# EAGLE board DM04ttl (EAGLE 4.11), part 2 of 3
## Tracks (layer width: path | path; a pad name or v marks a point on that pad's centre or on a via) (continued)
DATA_OUT  (via drill 0.61) (continued)
  Bottom 0.254: 44.45,128.27 30.48,128.27 26.67,132.08 IC19.4 | 44.45,128.27 46.35,128.27 46.99,127.64 49.53,127.64 51.44,125.73 58.42,125.73 59.69,124.46 IC21.7 | IC23.7 97.79,124.46 98.42,123.83 v100.33,123.83 102.23,123.83 102.87,123.19 128.27,123.19 129.54,124.46 130.81,124.46 IC25.7 133.35,124.46 135.25,124.46 136.53,123.19 165.1,123.19 166.37,124.46 IC27.7 | 44.45,128.27 44.45,133.35 46.35,133.35 48.9,135.89 69.85,135.89 72.39,138.43 v100.33,138.43
DATA_OUT0\  (via drill 0.61)
  Top 0.254: v179.07,120.65 178.44,120.02 178.44,99.69 176.53,97.79 173.35,97.79 173.35,95.89 173.99,95.25 180.34,95.25 180.34,68.58 178.44,66.67 v178.44,46.99
  Bottom 0.254: 177.16,46.35 176.53,46.99 166.37,46.99 165.74,46.35 164.47,46.35 163.83,45.72 RN13.10 | 177.16,46.35 177.16,43.81 154.31,43.81 153.67,43.18 153.03,43.18 ADDRESS0.X | v179.07,120.65 177.8,120.65 176.53,121.92 IC27.13 | v178.44,46.99 177.8,46.35 177.16,46.35
DATA_OUT1\  (via drill 0.61)
  Top 0.254: v144.78,121.92 146.69,120.02 v146.69,45.72
  Bottom 0.254: 124.46,44.45 123.19,43.18 117.47,43.18 ADDRESS1.X | 124.46,44.45 125.73,45.72 RN15.10 | v144.78,121.92 140.97,121.92 IC25.13 | v146.69,45.72 145.41,44.45 124.46,44.45
DATA_OUT2\  (via drill 0.61)
  Top 0.254: v109.86,45.72 v109.86,121.92
  Bottom 0.254: ADDRESS2.X 81.92,43.18 83.19,44.45 88.9,44.45 90.17,45.72 RN17.10 92.71,45.72 93.34,45.72 94.61,46.99 97.79,46.99 100.33,44.45 108.58,44.45 v109.86,45.72 | v109.86,121.92 105.41,121.92 IC23.13
DATA_OUT3\  (via drill 0.61)
  Top 0.254: v53.98,130.81 57.78,130.81 57.78,83.19 53.34,78.74 53.34,48.26 55.24,46.35 RN19.10
  Bottom 0.254: RN19.10 54.61,45.72 53.98,45.09 48.26,45.09 46.35,43.18 ADDRESS3.X | v53.98,130.81 57.15,130.81 59.69,128.27 62.23,128.27 67.94,122.56 IC21.13
DATA_OUT\  (via drill 0.61)
  Top 0.254: v36.83,187.96 v36.83,138.43
  Bottom 0.254: v36.83,138.43 27.94,138.43 26.67,137.16 IC19.2 | v36.83,187.96 36.83,201.93 208.28,201.93 227.33,182.88 227.33,43.81 218.44,43.81 ADDRESS.X
DB0
  Bottom 0.254: IC30.13 192.41,132.72 191.13,133.99 180.97,133.99 176.53,129.54 IC27.16 173.99,129.54 172.72,130.81 137.16,130.81 | IC21.16 69.85,129.54 71.12,128.27 101.6,128.27 102.87,129.54 IC23.16 105.41,129.54 106.68,130.81 137.16,130.81 | 137.16,130.81 138.43,129.54 IC25.16
DB0-0\
  Top 0.254: IC27.4 166.37,132.08 163.83,134.62 RN1.3
  Bottom 0.254: DATA0.F 153.03,132.08 154.31,133.35 160.02,133.35 161.29,134.62 RN1.3
DB0-1\
  Bottom 0.254: IC25.4 130.81,132.08 128.27,134.62 RN5.3 125.73,134.62 120.02,134.62 117.47,132.08 DATA1.F
DB0-2\
  Bottom 0.254: 94.61,132.72 92.71,134.62 RN7.3 | 94.61,132.72 95.25,132.08 IC23.4 | 94.61,132.72 92.71,130.81 83.19,130.81 81.92,132.08 DATA2.F
DB0-3\
  Bottom 0.254: IC21.4 59.69,132.08 57.15,134.62 RN9.3 54.61,134.62 48.9,134.62 46.35,132.08 DATA3.F
DB0\
  Bottom 0.254: IC30.15 198.75,131.44 200.03,130.18 214.63,130.18 215.26,130.81 216.53,130.81 217.81,132.08 DATA.F
DB1  (via drill 0.61)
  Top 0.254: v185.42,125.73 185.42,128.27 187.96,130.81 IC30.11
  Bottom 0.254: IC21.12 69.85,119.38 71.12,120.65 100.33,120.65 101.6,119.38 102.87,119.38 IC23.12 105.41,119.38 106.68,120.65 136.53,120.65 137.79,119.38 138.43,119.38 IC25.12 140.97,119.38 142.24,120.65 172.72,120.65 173.99,119.38 IC27.12 176.53,119.38 179.07,119.38 v185.42,125.73
DB1-0\
  Top 0.254: IC27.8 167,122.56 165.74,123.83 165.74,131.44 163.83,133.35 160.66,133.35 160.66,131.44 161.93,130.18 RN1.5
  Bottom 0.254: DATA0.L 153.03,127 154.31,128.27 157.48,128.27 158.75,129.54 161.29,129.54 RN1.5
DB1-1\  (via drill 0.61)
  Top 0.254: v133.99,114.3 133.99,120.02 132.72,121.28 IC25.8 | v128.27,114.94 128.91,115.57 128.91,127.64 127.64,128.91 RN5.5
  Bottom 0.254: v133.99,114.3 133.35,114.94 v128.27,114.94 | DATA1.L 117.47,127 120.02,129.54 125.73,129.54 RN5.5
DB1-2\  (via drill 0.61)
  Top 0.254: 89.53,129.54 85.09,129.54 v85.09,127 | 89.53,129.54 90.17,129.54 RN7.5 | v99.06,114.3 99.06,119.38 97.16,121.28 IC23.8 | v90.81,114.94 89.53,116.2 89.53,129.54
  Bottom 0.254: v85.09,127 81.92,127 DATA2.L | v99.06,114.3 98.42,114.94 v90.81,114.94
DB1-3\  (via drill 0.61)
  Top 0.254: v49.53,126.36 49.53,129.54 54.61,129.54 RN9.5
  Bottom 0.254: IC21.8 59.69,121.92 58.42,123.19 48.9,123.19 46.35,120.65 45.09,120.65 44.45,121.28 44.45,127 45.09,127 DATA3.L 46.35,127 48.9,127 v49.53,126.36
DB1\
  Bottom 0.254: IC30.9 183.51,131.44 186.69,128.27 216.53,128.27 217.81,127 DATA.L
DB2  (via drill 0.61)
  Top 0.254: v189.23,104.14 189.23,111.76 193.04,115.57 IC29.4
  Bottom 0.254: IC20.5 62.23,96.52 63.5,95.25 93.98,95.25 95.25,96.52 IC22.5 97.79,96.52 99.06,95.25 128.91,95.25 130.18,96.52 130.81,96.52 IC24.5 133.35,96.52 134.62,95.25 165.1,95.25 | 165.1,95.25 166.37,96.52 IC26.5 | v189.23,104.14 180.34,95.25 165.1,95.25
DB2-0\  (via drill 0.61)
  Top 0.254: v172.72,111.76 172.72,95.25 173.99,93.98 IC26.15 | v163.83,114.94 164.47,115.57 164.47,122.56 163.19,123.83 RN1.7 161.29,124.46 v158.75,121.92
  Bottom 0.254: v172.72,111.76 169.54,114.94 v163.83,114.94 | v158.75,121.92 153.03,121.92 DATA0.R
DB2-1\  (via drill 0.61)
  Top 0.254: RN5.7 125.73,124.46 v123.19,121.92 123.19,116.84 v128.27,111.76 | v137.16,107.31 137.16,96.52 139.06,94.61 IC24.15
  Bottom 0.254: v123.19,121.92 117.47,121.92 DATA1.R | v137.16,107.31 132.72,111.76 v128.27,111.76
DB2-2\  (via drill 0.61)
  Top 0.254: v101.6,120.65 101.6,96.52 103.5,94.61 IC22.15 | v88.27,124.46 v88.27,121.92
  Bottom 0.254: v101.6,120.65 99.06,123.19 93.98,123.19 92.71,124.46 RN7.7 90.17,124.46 v88.27,124.46 | v88.27,121.92 81.92,121.92 DATA2.R
DB2-3\  (via drill 0.61)
  Top 0.254: v66.04,119.38 66.04,114.3 65.41,113.67 65.41,97.16 67.94,94.61 IC20.15
  Bottom 0.254: v66.04,119.38 62.23,123.19 59.69,123.19 58.42,124.46 57.15,124.46 RN9.7 55.24,123.83 48.26,123.83 46.35,121.92 DATA3.R
DB2\  (via drill 0.61)
  Top 0.254: v201.93,120.65 198.75,117.47 IC29.2
  Bottom 0.254: v201.93,120.65 216.53,120.65 217.81,121.92 DATA.R
DB3
  Bottom 0.254: IC29.11 187.32,108.58 186.06,107.31 182.25,107.31 176.53,101.6 IC26.18 173.99,101.6 172.72,102.87 137.16,102.87 | 101.6,102.87 71.12,102.87 69.85,101.6 IC20.18 | 101.6,102.87 102.87,101.6 IC22.18 | 137.16,102.87 138.43,101.6 IC24.18 | 137.16,102.87 101.6,102.87
DB3-0\  (via drill 0.61)
  Top 0.254: 160.66,116.84 160.66,117.47 161.93,118.75 RN1.9 | 160.66,116.84 160.66,116.2 164.47,112.39 164.47,107.31 167,104.78 IC26.2 | v160.02,116.84 160.66,116.84
  Bottom 0.254: v160.02,116.84 153.03,116.84 DATA0.V
DB3-1\  (via drill 0.61)
  Top 0.254: v134.62,106.68 132.72,104.78 IC24.2 | v124.46,116.84 126.36,118.75 RN5.9
  Bottom 0.254: v134.62,106.68 133.35,107.95 132.72,107.95 130.81,109.86 130.18,109.86 128.27,107.95 122.56,107.95 117.47,113.03 116.2,113.03 115.57,113.67 115.57,116.84 116.2,116.84 DATA1.V 117.47,116.84 v124.46,116.84
DB3-2\  (via drill 0.61)
  Top 0.254: v100.33,108.58 v100.33,104.14 | v85.72,119.38 84.45,118.11 v84.45,116.84
  Bottom 0.254: v100.33,104.14 97.79,104.14 IC22.2 | v100.33,108.58 98.42,110.49 84.45,110.49 81.92,113.03 80.64,113.03 80.01,113.67 80.01,116.84 80.64,116.84 DATA2.V 81.92,116.84 v84.45,116.84 | v85.72,119.38 90.17,119.38 RN7.9
DB3-3\  (via drill 0.61)
  Top 0.254: v63.5,119.38 63.5,106.68 61.59,104.78 IC20.2
  Bottom 0.254: v63.5,119.38 62.23,120.65 58.42,120.65 57.15,119.38 RN9.9 55.24,118.75 48.26,118.75 46.35,116.84 DATA3.V
DB3\  (via drill 0.61)
  Top 0.254: v189.23,120.02 189.23,115.57 183.51,109.86 IC29.9
  Bottom 0.254: v189.23,120.02 189.87,119.38 214,119.38 215.26,118.11 216.53,118.11 217.81,116.84 DATA.V
DB4
  Top 0.254: IC26.16 176.53,96.52 186.69,106.68 186.69,111.76 190.5,115.57 IC29.5
  Bottom 0.254: 101.6,97.79 71.12,97.79 69.85,96.52 IC20.16 | 101.6,97.79 102.87,96.52 IC22.16 | 137.16,97.79 138.43,96.52 IC24.16 | 137.16,97.79 101.6,97.79 | 137.16,97.79 172.72,97.79 173.99,96.52 IC26.16
DB4-0\
  Top 0.254: IC26.4 167,99.69 164.47,102.23 164.47,104.78 163.19,106.05 RN2.2
  Bottom 0.254: DATA0.Z 153.03,111.76 155.57,109.22 158.75,109.22 161.29,106.68 RN2.2
DB4-1\  (via drill 0.61)
  Top 0.254: v130.81,108.58 130.18,107.95 130.18,100.97 131.44,99.69 IC24.4
  Bottom 0.254: v130.81,108.58 128.91,106.68 128.27,106.68 RN6.2 125.73,106.68 122.56,106.68 117.47,111.76 DATA1.Z
DB4-2\  (via drill 0.61)
  Top 0.254: v99.06,106.68 99.06,101.6 97.16,99.69 IC22.4
  Bottom 0.254: v99.06,106.68 97.79,107.95 93.98,107.95 92.71,106.68 RN8.2 90.17,106.68 87,109.86 83.82,109.86 81.92,111.76 DATA2.Z
DB4-3\  (via drill 0.61)
  Top 0.254: v59.69,108.58 59.05,107.95 59.05,100.97 60.33,99.69 IC20.4 | v49.53,106.68 49.53,107.31 45.72,111.12 DATA3.Z
  Bottom 0.254: v59.69,108.58 57.78,106.68 57.15,106.68 RN10.2 54.61,106.68 v49.53,106.68
DB4\
  Bottom 0.254: IC29.7 186.06,116.2 189.23,113.03 216.53,113.03 217.81,111.76 DATA.Z
DB5  (via drill 0.61)
  Top 0.254: v179.07,87 177.16,88.9 177.16,89.53 175.9,90.81 IC26.14
  Bottom 0.254: IC20.14 69.85,91.44 71.12,92.71 101.6,92.71 102.87,91.44 IC22.14 105.41,91.44 106.68,92.71 135.89,92.71 137.16,91.44 138.43,91.44 IC24.14 140.97,91.44 142.24,92.71 172.72,92.71 173.99,91.44 IC26.14 | v179.07,87 189.87,87 192.41,84.45 IC28.13
DB5-0\  (via drill 0.61)
  Top 0.254: IC26.6 168.28,94.61 169.54,95.89 v169.54,105.41 169.54,107.31 168.91,107.95 165.1,107.95 165.1,129.54 163.19,131.44 RN1.4
  Bottom 0.254: v169.54,105.41 154.31,105.41 153.03,106.68 DATA0.DD
DB5-1\  (via drill 0.61)
  Top 0.254: 123.19,139.7 124.46,138.43 124.46,134.62 126.36,132.72 RN5.4 | 123.19,139.7 115.57,139.7 115.57,111.12 116.2,110.49 118.11,110.49 118.11,108.58 116.84,107.31 DATA1.DD | v135.25,140.97 135.25,120.02 135.89,119.38 135.89,97.79 132.72,94.61 IC24.6 | v124.46,140.97 123.19,139.7
  Bottom 0.254: v135.25,140.97 v124.46,140.97
DB5-2\  (via drill 0.61)
  Top 0.254: v97.79,77.47 97.79,82.55 98.42,83.19 98.42,92.08 97.16,93.34 IC22.6 | v74.3,77.47 v74.3,106.68 | v82.55,133.35 82.55,108.58 81.28,107.31 DATA2.DD
  Bottom 0.254: v74.3,77.47 v97.79,77.47 | v74.3,106.68 75.56,107.95 79.38,107.95 80.64,106.68 DATA2.DD | v82.55,133.35 88.9,133.35 90.17,132.08 RN7.4
DB5-3\  (via drill 0.61)
  Top 0.254: v71.75,106.68 71.75,92.71 67.31,92.71 64.77,95.25 64.77,99.06 63.5,99.06 62.23,97.79 62.87,97.16 62.87,95.89 61.59,94.61 IC20.6 | RN9.4 54.61,132.08 46.99,132.08 46.99,131.44 46.35,130.81 44.45,130.81 44.45,108.58 45.72,107.31 DATA3.DD
  Bottom 0.254: v71.75,106.68 70.48,107.95 61.59,107.95 59.69,109.86 59.05,109.86 57.15,107.95 47.62,107.95 46.35,106.68 DATA3.DD
DB5\
  Bottom 0.254: IC28.15 198.75,84.45 203.2,88.9 214,88.9 215.26,90.17 219.07,90.17 219.71,90.81 219.71,106.05 218.44,106.05 DATA.DD
DB6
  Bottom 0.254: IC20.7 62.23,91.44 63.5,90.17 93.34,90.17 94.61,91.44 95.25,91.44 IC22.7 97.79,91.44 98.42,90.81 102.23,90.81 102.87,90.17 129.54,90.17 130.81,91.44 IC24.7 133.35,91.44 134.62,90.17 165.1,90.17 | 165.1,90.17 166.37,91.44 IC26.7 | 165.1,90.17 176.53,90.17 177.16,89.53 191.13,89.53 192.41,90.81 IC28.4
DB6-0\  (via drill 0.61)
  Top 0.254: v170.18,88.27 169.54,87.63 166.37,87.63 165.1,88.9 165.1,93.98 163.19,95.89 RN2.6 | v156.21,101.6 157.48,100.33 v157.48,96.52
  Bottom 0.254: v170.18,88.27 170.81,88.9 173.99,88.9 IC26.13 | v156.21,101.6 153.03,101.6 DATA0.JJ | v157.48,96.52 161.29,96.52 RN2.6
DB6-1\  (via drill 0.61)
  Top 0.254: 121.28,97.79 117.47,101.6 DATA1.JJ | 121.28,97.79 v122.56,96.52 | v141.6,79.38 141.6,87 140.34,88.27 IC24.13 | v128.27,79.38 121.28,86.36 121.28,97.79
  Bottom 0.254: v122.56,96.52 125.73,96.52 RN6.6 | v128.27,79.38 v141.6,79.38
DB6-2\  (via drill 0.61)
  Top 0.254: v88.27,101.6 88.27,99.69 90.81,97.16 RN8.6 | v101.6,81.28 101.6,86.36 103.5,88.27 IC22.13 | v84.45,82.55 83.82,83.19 83.82,93.34 83.19,93.98 83.19,99.06 81.28,100.97 DATA2.JJ
  Bottom 0.254: v88.27,101.6 81.92,101.6 DATA2.JJ | v101.6,81.28 100.33,80.01 87,80.01 v84.45,82.55
DB6-3\  (via drill 0.61)
  Top 0.254: v66.04,91.44 67.94,89.53 IC20.13 | v50.16,96.52 v50.16,100.97
  Bottom 0.254: v66.04,91.44 62.23,95.25 58.42,95.25 57.15,96.52 RN10.6 54.61,96.52 v50.16,96.52 | v50.16,100.97 46.99,100.97 46.35,101.6 DATA3.JJ
DB6\  (via drill 0.61)
  Top 0.254: v204.47,97.79 198.75,92.08 IC28.2
  Bottom 0.254: v204.47,97.79 207.01,100.33 216.53,100.33 217.81,101.6 DATA.JJ
DB7  (via drill 0.61)
  Top 0.254: v71.75,77.47 71.75,83.19 69.22,85.72 IC20.12
  Bottom 0.254: 177.16,85.72 175.9,85.72 IC26.12 | 177.16,85.72 186.06,85.72 187.32,84.45 IC28.11 | v71.75,77.47 73.03,76.2 103.5,76.2 107.95,80.64 107.95,82.55 | 107.95,82.55 107.95,85.72 104.78,85.72 IC22.12 | 141.6,81.28 141.6,80.64 120.65,80.64 118.75,82.55 107.95,82.55 | 141.6,81.28 141.6,84.45 140.34,85.72 IC24.12 | 177.16,85.72 177.16,81.28 141.6,81.28
DB7-0\  (via drill 0.61)
  Top 0.254: IC26.8 167,89.53 165.74,90.81 165.74,98.42 163.19,100.97 RN2.4 161.93,100.97 158.75,97.79 158.75,95.25 157.48,95.25 v156.21,96.52
  Bottom 0.254: v156.21,96.52 153.03,96.52 DATA0.NN
DB7-1\  (via drill 0.61)
  Top 0.254: 125.09,95.25 125.09,99.69 126.36,100.97 RN6.4 | v125.09,87.63 125.09,95.25 | 125.09,95.25 117.47,102.87 116.2,102.87 115.57,102.23 115.57,98.42 116.84,97.16 DATA1.NN
  Bottom 0.254: v125.09,87.63 129.54,87.63 130.81,88.9 IC24.8
DB7-2\  (via drill 0.61)
  Top 0.254: v82.55,87.63 82.55,94.61 81.28,95.89 DATA2.NN | v88.9,87.63 88.9,80.01 92.08,80.01 93.34,81.28 93.34,99.69 92.08,100.97 RN8.4
  Bottom 0.254: v82.55,87.63 v88.9,87.63 93.98,87.63 95.25,88.9 IC22.8
DB7-3\  (via drill 0.61)
  Top 0.254: v53.98,92.71 v53.98,97.79 53.98,99.69 55.24,100.97 RN10.4
  Bottom 0.254: v53.98,92.71 57.15,92.71 60.33,89.53 IC20.8 | v53.98,97.79 47.62,97.79 46.35,96.52 DATA3.NN
DB7\  (via drill 0.61)
  Top 0.254: v189.23,94.61 189.23,90.17 183.51,84.45 IC28.9
  Bottom 0.254: v189.23,94.61 189.87,95.25 216.53,95.25 217.81,96.52 DATA.NN
DB8  (via drill 0.61)
  Top 0.254: v188.59,88.27 190.5,90.17 IC28.5
  Bottom 0.254: IC20.9 62.23,86.36 62.87,85.72 66.67,85.72 67.31,85.09 93.98,85.09 95.25,86.36 IC22.9 97.79,86.36 99.06,87.63 107.31,87.63 109.86,85.09 129.54,85.09 130.81,86.36 IC24.9 133.35,86.36 134.62,87.63 140.97,87.63 143.51,85.09 163.83,85.09 164.47,85.72 165.74,85.72 166.37,86.36 IC26.9 168.28,85.72 170.18,85.72 172.09,87.63 176.53,87.63 177.16,88.27 v188.59,88.27
DB8-0\  (via drill 0.61)
  Top 0.254: v165.1,82.55 163.19,84.45 163.19,85.72 RN2.10 161.29,86.36 160.66,86.36 159.38,87.63 v159.38,91.44
  Bottom 0.254: v165.1,82.55 172.72,82.55 173.99,83.82 IC26.11 | v159.38,91.44 153.03,91.44 DATA0.TT
DB8-1\  (via drill 0.61)
  Top 0.254: v122.56,91.44 122.56,86.36 125.73,86.36 RN6.10 127.64,85.72 127.64,83.19 v128.27,82.55
  Bottom 0.254: v122.56,91.44 117.47,91.44 DATA1.TT | v128.27,82.55 137.16,82.55 138.43,83.82 IC24.11
DB8-2\  (via drill 0.61)
  Top 0.254: v88.27,91.44 88.27,89.53 90.81,87 RN8.10 92.08,85.72 v92.08,81.28
  Bottom 0.254: v88.27,91.44 81.92,91.44 DATA2.TT | v92.08,81.28 100.33,81.28 102.87,83.82 IC22.11
DB8-3\
  Bottom 0.254: DATA3.TT 46.35,91.44 49.53,88.27 52.7,88.27 54.61,86.36 RN10.10 57.15,86.36 58.42,85.09 66.04,85.09 67.31,83.82 IC20.11
DB8\
  Bottom 0.254: IC28.7 186.06,92.08 187.32,93.34 214.63,93.34 215.26,92.71 216.53,92.71 217.81,91.44 DATA.TT
DB9
  Bottom 0.254: IC30.4 192.41,139.06 191.13,137.79 179.71,137.79 176.53,134.62 IC27.18 173.99,134.62 172.72,135.89 137.16,135.89 | 101.6,135.89 71.12,135.89 69.85,134.62 IC21.18 | 101.6,135.89 102.87,134.62 IC23.18 | 137.16,135.89 138.43,134.62 IC25.18 | 137.16,135.89 101.6,135.89
DB9-0\  (via drill 0.61)
  Top 0.254: v160.02,134.62 161.93,136.53 RN1.2
  Bottom 0.254: RN1.2 163.83,137.16 166.37,137.16 IC27.2 | v160.02,134.62 153.03,134.62 DATA0.D
DB9-1\  (via drill 0.61)
  Top 0.254: v120.02,137.16 117.47,134.62 DATA1.D
  Bottom 0.254: IC25.2 130.81,137.16 128.27,137.16 RN5.2 125.73,137.16 v120.02,137.16
DB9-2\  (via drill 0.61)
  Top 0.254: v85.72,134.62 v88.27,137.16
  Bottom 0.254: IC23.2 95.25,137.16 92.71,137.16 RN7.2 90.17,137.16 v88.27,137.16 | v85.72,134.62 81.92,134.62 DATA2.D
DB9-3\
  Bottom 0.254: IC21.2 59.69,137.16 57.15,137.16 RN9.2 54.61,137.16 48.9,137.16 46.35,134.62 DATA3.D
DB9\
  Bottom 0.254: IC30.2 198.75,139.06 201.93,135.89 216.53,135.89 217.81,134.62 DATA.D
DB10  (via drill 0.61)
  Top 0.254: v184.15,129.54 184.15,133.35 189.87,139.06 IC30.5
  Bottom 0.254: 101.6,125.73 71.12,125.73 69.85,124.46 IC21.14 | 101.6,125.73 102.87,124.46 IC23.14 | 137.16,125.73 138.43,124.46 IC25.14 | 137.16,125.73 101.6,125.73 | 137.16,125.73 168.91,125.73 169.54,125.09 173.35,125.09 173.99,124.46 IC27.14 176.53,124.46 179.07,124.46 v184.15,129.54
DB10-0\  (via drill 0.61)
  Top 0.254: v164.47,84.45 164.47,89.53 163.19,90.81 RN2.8 | v171.45,85.09 171.45,123.19 172.09,123.83 v172.09,126.36 | v158.75,128.27 v157.48,129.54
  Bottom 0.254: v164.47,84.45 165.1,85.09 v171.45,85.09 | v172.09,126.36 171.45,127 168.91,127 IC27.6 166.37,127 165.74,127 164.47,128.27 v158.75,128.27 | v157.48,129.54 153.03,129.54 DATA0.J
DB10-1\  (via drill 0.61)
  Top 0.254: 118.11,129.54 118.75,128.91 118.75,107.95 128.27,107.95 128.91,107.31 128.91,93.34 127.64,92.08 RN6.8 | 118.11,129.54 117.47,129.54 DATA1.J | v133.99,138.43 133.99,128.91 132.72,127.64 IC25.6 | v123.19,138.43 118.11,133.35 118.11,129.54
  Bottom 0.254: v133.99,138.43 v123.19,138.43
DB10-2\  (via drill 0.61)
  Top 0.254: 87,113.67 87,123.19 83.82,126.36 83.82,133.99 81.92,135.89 80.01,135.89 80.01,131.44 81.28,130.18 DATA2.J | 87,113.67 87,99.69 89.53,97.16 89.53,93.34 90.81,92.08 RN8.8 | v100.33,114.3 100.33,119.38 99.06,120.65 99.06,124.46 97.16,126.36 IC23.6 | 87,113.67 v88.27,113.67
  Bottom 0.254: v100.33,114.3 99.06,113.03 98.42,113.03 97.16,114.3 91.44,114.3 90.81,113.67 v88.27,113.67
DB10-3\
  Top 0.254: RN10.8 54.61,91.44 52.07,91.44 52.07,113.03 52.7,113.67 52.7,121.92 45.72,128.91 DATA3.J
  Bottom 0.254: IC21.6 59.69,127 58.42,128.27 47.62,128.27 46.35,129.54 DATA3.J
DB10\
  Bottom 0.254: IC30.7 186.06,140.34 187.32,141.6 215.9,141.6 219.71,137.79 219.71,130.18 218.44,130.18 DATA.J
DB11
  Bottom 0.254: IC20.3 62.23,101.6 62.87,100.97 66.67,100.97 67.31,100.33 93.34,100.33 94.61,101.6 95.25,101.6 IC22.3 97.79,101.6 99.06,100.33 128.91,100.33 130.18,101.6 130.81,101.6 IC24.3 133.35,101.6 134.62,100.33 165.1,100.33 | 165.1,100.33 166.37,101.6 IC26.3 | 165.1,100.33 184.15,100.33 192.41,108.58 IC29.13
DB11-0\  (via drill 0.61)
  Top 0.254: IC26.17 175.9,99.69 177.8,101.6 177.8,144.15 169.54,152.4 163.83,152.4 163.83,143.51 158.75,138.43 158.75,130.81 161.93,127.64 RN1.6 161.29,127 v158.75,124.46
  Bottom 0.254: v158.75,124.46 153.03,124.46 DATA0.N
DB11-1\  (via drill 0.61)
  Top 0.254: v123.19,124.46 125.73,127 RN5.6 | v143.51,128.27 v143.51,99.06
  Bottom 0.254: v123.19,124.46 117.47,124.46 DATA1.N | v143.51,99.06 140.97,99.06 IC24.17 | v143.51,128.27 129.54,128.27 128.27,127 RN5.6
DB11-2\  (via drill 0.61)
  Top 0.254: v106.68,82.55 106.68,96.52 104.78,98.42 IC22.17 | v77.47,80.64 v77.47,123.19 | v88.27,127 87,125.73 v87,124.46
  Bottom 0.254: v106.68,82.55 103.5,79.38 78.74,79.38 v77.47,80.64 | v77.47,123.19 79.38,123.19 80.64,124.46 DATA2.N 81.92,124.46 v87,124.46 | v88.27,127 90.17,127 RN7.6
DB11-3\  (via drill 0.61)
  Top 0.254: v53.34,100.33 53.98,100.97 53.98,125.09 | 53.98,125.09 55.24,126.36 RN9.6 | 53.98,125.09 v50.8,125.09
  Bottom 0.254: v53.34,100.33 66.04,100.33 67.31,99.06 IC20.17 | v50.8,125.09 46.99,125.09 46.35,124.46 DATA3.N
DB11\
  Bottom 0.254: IC29.15 198.75,108.58 200.03,107.31 212.09,107.31 215.26,110.49 219.07,110.49 220.34,111.76 220.34,123.83 218.44,123.83 DATA.N
GND  (via drill 0.61)
  Top 0.635: v64.14,134.62 64.14,139.7 62.23,141.6 C21.2 | DATA2.B 80.64,137.16 79.38,137.16 DATA2.A 78.74,136.53 78.74,135.25 DATA2.C 78.74,133.99 78.74,132.72 DATA2.E 78.74,131.44 78.74,130.18 DATA2.H 78.74,128.91 78.74,127.64 DATA2.K 78.74,126.36 78.74,125.09 DATA2.M 78.74,123.83 78.74,122.56 DATA2.P 78.74,121.28 78.74,120.02 DATA2.S 78.74,118.75 78.74,117.47 DATA2.U 78.74,116.2 78.74,114.94 DATA2.W 78.74,113.67 78.74,112.39 DATA2.Y 78.74,111.12 78.74,109.86 DATA2.AA 78.74,108.58 78.74,107.31 DATA2.CC 78.74,106.05 78.74,104.78 DATA2.EE 78.74,103.5 78.74,102.23 DATA2.HH 78.74,100.97 78.74,99.69 DATA2.KK 78.74,98.42 78.74,97.16 DATA2.MM 78.74,95.89 78.74,94.61 DATA2.PP 78.74,93.34 78.74,92.08 DATA2.SS 78.74,90.81 78.74,89.53 DATA2.UU 78.74,88.27 v78.74,83.82 78.74,66.67 ADDRESS2.A | C20.2 62.23,109.86 v62.23,111.76 62.23,116.84 IC21.10 | IC8.10 95.89,12.06 94.61,10.79 94.61,7.62 C96.- 92.71,6.99 78.74,6.99 78.74,17.14 ADDRESS2.UU 78.74,18.41 78.74,19.68 ADDRESS2.SS 78.74,20.95 78.74,22.23 ADDRESS2.PP 78.74,23.5 78.74,24.77 ADDRESS2.MM 78.74,26.04 78.74,27.3 ADDRESS2.KK 78.74,28.57 78.74,29.84 ADDRESS2.HH 78.74,31.11 78.74,32.38 ADDRESS2.EE 78.74,33.66 78.74,34.92 ADDRESS2.CC 78.74,36.2 78.74,37.47 ADDRESS2.AA 78.74,38.73 78.74,40.01 ADDRESS2.Y 78.74,41.27 78.74,42.55 ADDRESS2.W 78.74,43.81 78.74,45.09 ADDRESS2.U 78.74,46.35 78.74,47.62 ADDRESS2.S 78.74,48.9 78.74,50.16 ADDRESS2.P 78.74,51.44 78.74,52.7 ADDRESS2.M 78.74,53.98 78.74,55.24 ADDRESS2.K 78.74,56.52 78.74,57.78 ADDRESS2.H 78.74,59.05 78.74,60.33 ADDRESS2.E 78.74,61.59 78.74,62.87 ADDRESS2.C 78.74,64.14 78.74,65.41 ADDRESS2.A
  Top 0.635: 61.59,40.64 61.59,45.09 IC7.10 | 61.59,40.64 61.59,39.37 62.23,38.73 C6.2 | ADDRESS2.B 80.64,66.04 79.38,66.04 ADDRESS2.A | v62.23,40.64 61.59,40.64 | 10.79,32.38 10.79,23.5 12.7,21.59 IC3.8 | 10.79,32.38 12.7,34.29 IC1.7 12.7,36.83 12.7,38.1 16.51,38.1 20.32,41.91 IC4.12 | 10.79,47.62 12.7,49.53 IC4.8 | 10.79,32.38 10.79,47.62 | 10.79,47.62 10.79,62.87 12.7,64.77 IC2.7 | ADDRESS3.VV 45.09,17.78 43.81,17.78 ADDRESS3.UU 43.18,18.41 43.18,19.68 ADDRESS3.SS 43.18,20.95 43.18,22.23 ADDRESS3.PP 43.18,23.5 43.18,24.77 ADDRESS3.MM 43.18,26.04 43.18,27.3 ADDRESS3.KK 43.18,28.57 43.18,29.84 ADDRESS3.HH 43.18,31.11 43.18,32.38 ADDRESS3.EE 43.18,33.66 43.18,34.92 ADDRESS3.CC 43.18,36.2 43.18,37.47 ADDRESS3.AA 43.18,38.73 43.18,40.01 ADDRESS3.Y 43.18,41.27 43.18,42.55 ADDRESS3.W 43.18,43.81 43.18,45.09 ADDRESS3.U 43.18,46.35 43.18,47.62 ADDRESS3.S 43.18,48.9 43.18,50.16 ADDRESS3.P 43.18,51.44 43.18,52.7 ADDRESS3.M 43.18,53.98 43.18,55.24 ADDRESS3.K 43.18,56.52 43.18,57.78 ADDRESS3.H 43.18,59.05 43.18,60.33 ADDRESS3.E 43.18,61.59 43.18,62.87 ADDRESS3.C 43.18,64.14 43.18,65.41 ADDRESS3.A 43.18,66.67 43.18,88.27 DATA3.UU | IC31.5 58.42,194.31 57.15,195.58 50.8,195.58 50.8,194.31 IC31.8 50.8,191.77 50.8,191.13 48.26,188.59 48.26,178.44 45.72,175.9 SV1.2 45.09,175.26 43.18,173.35 43.18,137.79 DATA3.A | DATA3.A 43.18,136.53 43.18,135.25 DATA3.C 43.18,133.99 43.18,132.72 DATA3.E 43.18,131.44 43.18,130.18 DATA3.H 43.18,128.91 43.18,127.64 DATA3.K 43.18,126.36 43.18,125.09 DATA3.M 43.18,123.83 43.18,122.56 DATA3.P 43.18,121.28 43.18,120.02 DATA3.S 43.18,118.75 43.18,117.47 DATA3.U 43.18,116.2 43.18,114.94 DATA3.W 43.18,113.67 43.18,112.39 DATA3.Y 43.18,111.12 43.18,109.86 DATA3.AA 43.18,108.58 43.18,107.31 DATA3.CC 43.18,106.05 43.18,104.78 DATA3.EE 43.18,103.5 43.18,102.23 DATA3.HH 43.18,100.97 43.18,99.69 DATA3.KK 43.18,98.42 43.18,97.16 DATA3.MM 43.18,95.89 43.18,94.61 DATA3.PP 43.18,93.34 43.18,92.08 DATA3.SS 43.18,90.81 43.18,89.53 DATA3.UU
  Top 0.635: DATA3.A 43.81,137.16 45.09,137.16 DATA3.B 45.72,137.79 50.8,142.88 50.8,158.75 53.34,161.29 IC34.7 | C19.2 26.67,141.6 26.67,140.97 26.04,140.34 IC19.1 26.67,139.7 27.94,138.43 27.94,123.19 26.67,121.92 IC19.8 26.04,121.28 26.67,120.65 26.67,109.86 C18.2 26.67,108.58 26.67,107.95 26.04,107.31 IC18.1 | C9.2 97.79,71.75 96.52,73.03 96.52,83.19 IC22.10 | C7.2 62.23,71.75 62.23,83.82 IC20.10 | DATA3.UU 43.81,88.9 45.09,88.9 DATA3.VV | 168.28,42.55 168.28,45.09 IC13.10 | 168.28,42.55 168.28,39.37 168.91,38.73 C12.2 | 190.5,29.21 182.88,21.59 IC14.8 | 190.5,29.21 190.5,36.83 IC15.12 | v171.45,42.55 168.28,42.55 | IC16.12 190.5,62.23 200.66,52.07 200.66,46.99 IC15.1 | 190.5,80.01 182.88,72.39 IC16.8 | 190.5,80.01 190.5,82.55 IC28.12 190.5,85.09 194.31,88.9 200.03,88.9 200.03,90.81 IC28.1 | ADDRESS.UU 215.9,18.41 215.9,19.68 ADDRESS.SS 215.9,20.95 215.9,22.23 ADDRESS.PP 215.9,23.5 215.9,24.77 ADDRESS.MM 215.9,26.04 215.9,27.3 ADDRESS.KK 215.9,28.57 215.9,29.84 ADDRESS.HH 215.9,31.11 215.9,32.38 ADDRESS.EE 215.9,33.66 215.9,34.92 ADDRESS.CC 215.9,36.2 215.9,37.47 ADDRESS.AA 215.9,38.73 215.9,40.01 ADDRESS.Y 215.9,41.27 215.9,42.55 ADDRESS.W 215.9,43.81 215.9,45.09 ADDRESS.U 215.9,46.35 215.9,47.62 ADDRESS.S 215.9,48.9 215.9,50.16 ADDRESS.P 215.9,51.44 215.9,52.7 ADDRESS.M 215.9,53.98 215.9,55.24 ADDRESS.K 215.9,56.52 215.9,57.78 ADDRESS.H 215.9,59.05 215.9,60.33 ADDRESS.E 215.9,61.59 215.9,62.87 ADDRESS.C 215.9,64.14 215.9,65.41 ADDRESS.A 216.53,66.04 217.81,66.04 ADDRESS.B | 190.5,80.01 200.66,80.01 200.66,72.39 IC16.1 | 190.5,29.21 200.66,29.21 200.66,21.59 IC14.1
  Top 0.635: IC28.8 182.88,92.71 190.5,100.33 190.5,107.95 IC29.12 190.5,110.49 194.31,114.3 200.03,114.3 200.03,116.2 IC29.1 201.29,116.2 201.29,115.57 202.56,114.3 C29.2 | DATA.UU 215.9,89.53 215.9,90.81 DATA.SS 215.9,92.08 215.9,93.34 DATA.PP 215.9,94.61 215.9,95.89 DATA.MM 215.9,97.16 215.9,98.42 DATA.KK 215.9,99.69 215.9,100.97 DATA.HH 215.9,102.23 215.9,103.5 DATA.EE 215.9,104.78 215.9,106.05 DATA.CC 215.9,107.31 215.9,108.58 DATA.AA 215.9,109.86 215.9,111.12 DATA.Y 215.9,112.39 215.9,113.67 DATA.W 215.9,114.94 215.9,116.2 DATA.U 215.9,117.47 215.9,118.75 DATA.S 215.9,120.02 215.9,121.28 DATA.P 215.9,122.56 215.9,123.83 DATA.M 215.9,125.09 215.9,126.36 DATA.K 215.9,127.64 215.9,128.91 DATA.H 215.9,130.18 215.9,131.44 DATA.E 215.9,132.72 215.9,133.99 DATA.C 215.9,135.25 215.9,136.53 DATA.A | IC30.8 182.88,140.97 177.8,146.05 177.8,149.22 BMB0.VV 177.16,149.86 175.9,149.86 BMB0.UU 175.26,150.5 175.26,151.76 BMB0.SS 175.26,153.03 175.26,154.31 BMB0.PP 175.26,155.57 175.26,156.84 BMB0.MM 175.26,158.12 175.26,159.38 BMB0.KK 175.26,160.66 175.26,161.93 BMB0.HH 175.26,163.19 175.26,164.47 BMB0.EE 175.26,165.74 175.26,167 BMB0.CC 175.26,168.28 175.26,169.54 BMB0.AA 175.26,170.81 175.26,172.09 BMB0.Y 175.26,173.35 175.26,174.62 BMB0.W 175.26,175.9 175.26,177.16 BMB0.U 175.26,178.44 175.26,179.71 BMB0.S 175.26,180.97 175.26,182.25 BMB0.P 175.26,183.51 175.26,184.78 BMB0.M 175.26,186.06 175.26,187.32 BMB0.K 175.26,188.59 175.26,189.87 BMB0.H 175.26,191.13 175.26,192.41 BMB0.E 175.26,193.68 175.26,194.94 BMB0.C 175.26,196.22 175.26,197.49 BMB0.A
  Top 0.635: BMB0.A 175.9,198.12 177.16,198.12 BMB0.B 178.44,198.12 189.87,198.12 BAC1.A | BAC1.VV 192.41,149.86 191.13,149.86 BAC1.UU 190.5,150.5 190.5,151.76 BAC1.SS 190.5,153.03 190.5,154.31 BAC1.PP 190.5,155.57 190.5,156.84 BAC1.MM 190.5,158.12 190.5,159.38 BAC1.KK 190.5,160.66 190.5,161.93 BAC1.HH 190.5,163.19 190.5,164.47 BAC1.EE 190.5,165.74 190.5,167 BAC1.CC 190.5,168.28 190.5,169.54 BAC1.AA 190.5,170.81 190.5,172.09 BAC1.Y 190.5,173.35 190.5,174.62 BAC1.W 190.5,175.9 190.5,177.16 BAC1.U 190.5,178.44 190.5,179.71 BAC1.S 190.5,180.97 190.5,182.25 BAC1.P 190.5,183.51 190.5,184.78 BAC1.M 190.5,186.06 190.5,187.32 BAC1.K 190.5,188.59 190.5,189.87 BAC1.H 190.5,191.13 190.5,192.41 BAC1.E 190.5,193.68 190.5,194.94 BAC1.C 190.5,196.22 190.5,197.49 BAC1.A | BAC1.A 191.13,198.12 192.41,198.12 BAC1.B 193.68,198.12 205.1,198.12 BAC0.A | C26.2 168.91,109.86 168.28,110.49 168.28,116.2 IC27.10 168.91,116.84 170.18,118.11 170.18,126.36 172.72,128.91 | 172.72,128.91 172.72,130.81 | 172.72,128.91 172.72,128.27 173.99,127 IC27.15 | 172.72,130.81 173.99,132.08 IC27.17 | 172.72,130.81 172.72,137.79 168.91,141.6 C27.2 | IC29.8 182.88,118.11 190.5,125.73 190.5,130.81 IC30.12 190.5,133.35 194.31,137.16 200.03,137.16 200.03,139.06 IC30.1 | BAC0.UU 206.38,149.86 207.65,149.86 BAC0.VV | BAC0.UU 205.74,150.5 205.74,151.76 BAC0.SS 205.74,153.03 205.74,154.31 BAC0.PP 205.74,155.57 205.74,156.84 BAC0.MM 205.74,158.12 205.74,159.38 BAC0.KK 205.74,160.66 205.74,161.93 BAC0.HH 205.74,163.19 205.74,164.47 BAC0.EE 205.74,165.74 205.74,167 BAC0.CC 205.74,168.28 205.74,169.54 BAC0.AA 205.74,170.81 205.74,172.09 BAC0.Y 205.74,173.35 205.74,174.62 BAC0.W 205.74,175.9 205.74,177.16 BAC0.U 205.74,178.44 205.74,179.71 BAC0.S 205.74,180.97 205.74,182.25 BAC0.P 205.74,183.51 205.74,184.78 BAC0.M 205.74,186.06 205.74,187.32 BAC0.K 205.74,188.59 205.74,189.87 BAC0.H 205.74,191.13 205.74,192.41 BAC0.E 205.74,193.68 205.74,194.94 BAC0.C 205.74,196.22 205.74,197.49 BAC0.A
  Top 0.635: BAC0.B 207.65,198.12 206.38,198.12 BAC0.A | C30.2 203.2,139.06 205.74,141.6 205.74,149.22 BAC0.UU | 97.16,40.64 97.16,45.09 IC9.10 | 97.16,40.64 97.16,39.37 97.79,38.73 C8.2 | v118.75,15.24 116.84,17.14 ADDRESS1.VV | ADDRESS1.UU 114.3,18.41 114.3,19.68 ADDRESS1.SS 114.3,20.95 114.3,22.23 ADDRESS1.PP 114.3,23.5 114.3,24.77 ADDRESS1.MM 114.3,26.04 114.3,27.3 ADDRESS1.KK 114.3,28.57 114.3,29.84 ADDRESS1.HH 114.3,31.11 114.3,32.38 ADDRESS1.EE 114.3,33.66 114.3,34.92 ADDRESS1.CC 114.3,36.2 114.3,37.47 ADDRESS1.AA 114.3,38.73 114.3,40.01 ADDRESS1.Y 114.3,41.27 114.3,42.55 ADDRESS1.W 114.3,43.81 114.3,45.09 ADDRESS1.U 114.3,46.35 114.3,47.62 ADDRESS1.S 114.3,48.9 114.3,50.16 ADDRESS1.P 114.3,51.44 114.3,52.7 ADDRESS1.M 114.3,53.98 114.3,55.24 ADDRESS1.K 114.3,56.52 114.3,57.78 ADDRESS1.H 114.3,59.05 114.3,60.33 ADDRESS1.E 114.3,61.59 114.3,62.87 ADDRESS1.C 114.3,64.14 114.3,65.41 ADDRESS1.A | v98.42,40.64 97.16,40.64 | C23.2 98.42,142.24 101.6,139.06 101.6,133.35 102.87,132.08 IC23.17 | C11.2 133.35,71.75 132.72,72.39 132.72,83.19 IC24.10 | 97.79,111.76 97.79,116.84 IC23.10 | 97.79,111.76 97.79,109.86 C22.2 | v100.33,111.76 97.79,111.76 | ADDRESS1.B 116.84,66.67 121.28,71.12 v121.28,83.82 116.84,88.27 DATA1.VV 116.2,88.9 114.94,88.9 DATA1.UU 114.3,89.53 114.3,90.81 DATA1.SS 114.3,92.08 114.3,93.34 DATA1.PP 114.3,94.61 114.3,95.89 DATA1.MM 114.3,97.16 114.3,98.42 DATA1.KK 114.3,99.69 114.3,100.97 DATA1.HH 114.3,102.23 114.3,103.5 DATA1.EE 114.3,104.78 114.3,106.05 DATA1.CC 114.3,107.31 114.3,108.58 DATA1.AA 114.3,109.86 114.3,111.12 DATA1.Y 114.3,112.39 114.3,113.67 DATA1.W 114.3,114.94 114.3,116.2 DATA1.U 114.3,117.47 114.3,118.75 DATA1.S 114.3,120.02 114.3,121.28 DATA1.P 114.3,122.56 114.3,123.83 DATA1.M 114.3,125.09 114.3,126.36 DATA1.K 114.3,127.64 114.3,128.91 DATA1.H 114.3,130.18 114.3,131.44 DATA1.E 114.3,132.72 114.3,133.99 DATA1.C 114.3,135.25 114.3,136.53 DATA1.A 114.3,137.79 111.12,140.97 111.12,146.69 106.05,151.76 106.05,163.83
  Top 0.635: IC12.10 167,12.06 164.47,9.53 164.47,7.62 C98.- 162.56,6.99 153.67,6.99 153.67,15.88 152.4,17.14 ADDRESS0.VV | C13.2 168.91,71.75 168.28,72.39 168.28,83.19 IC26.10 | 133.35,40.64 133.35,45.72 IC11.10 | 133.35,40.64 133.35,38.73 C10.2 | ADDRESS0.UU 149.86,18.41 149.86,19.68 ADDRESS0.SS 149.86,20.95 149.86,22.23 ADDRESS0.PP 149.86,23.5 149.86,24.77 ADDRESS0.MM 149.86,26.04 149.86,27.3 ADDRESS0.KK 149.86,28.57 149.86,29.84 ADDRESS0.HH 149.86,31.11 149.86,32.38 ADDRESS0.EE 149.86,33.66 149.86,34.92 ADDRESS0.CC 149.86,36.2 149.86,37.47 ADDRESS0.AA 149.86,38.73 149.86,40.01 ADDRESS0.Y 149.86,41.27 149.86,42.55 ADDRESS0.W 149.86,43.81 149.86,45.09 ADDRESS0.U 149.86,46.35 149.86,47.62 ADDRESS0.S 149.86,48.9 149.86,50.16 ADDRESS0.P 149.86,51.44 149.86,52.7 ADDRESS0.M 149.86,53.98 149.86,55.24 ADDRESS0.K 149.86,56.52 149.86,57.78 ADDRESS0.H 149.86,59.05 149.86,60.33 ADDRESS0.E 149.86,61.59 149.86,62.87 ADDRESS0.C 149.86,64.14 149.86,65.41 ADDRESS0.A 150.5,66.04 151.76,66.04 ADDRESS0.B 152.4,66.67 v152.4,71.12 149.86,73.66 149.86,88.27 DATA0.UU 149.86,89.53 149.86,90.81 DATA0.SS 149.86,92.08 149.86,93.34 DATA0.PP 149.86,94.61 149.86,95.89 DATA0.MM 149.86,97.16 149.86,98.42 DATA0.KK 149.86,99.69 149.86,100.97 DATA0.HH 149.86,102.23 149.86,103.5 DATA0.EE 149.86,104.78 149.86,106.05 DATA0.CC 149.86,107.31 149.86,108.58 DATA0.AA 149.86,109.86 149.86,111.12 DATA0.Y 149.86,112.39 149.86,113.67 DATA0.W 149.86,114.94 149.86,116.2 DATA0.U 149.86,117.47 149.86,118.75 DATA0.S 149.86,120.02 149.86,121.28 DATA0.P 149.86,122.56 149.86,123.83 DATA0.M 149.86,125.09 149.86,126.36 DATA0.K 149.86,127.64 149.86,128.91 DATA0.H 149.86,130.18 149.86,131.44 DATA0.E 149.86,132.72 149.86,133.99 DATA0.C 149.86,135.25 149.86,136.53 DATA0.A
  Top 0.635: v133.99,40.64 133.35,40.64 | DATA0.B 151.76,137.16 150.5,137.16 DATA0.A | 132.72,111.76 132.72,116.2 IC25.10 | 132.72,111.76 132.72,110.49 133.35,109.86 C24.2 | v134.62,111.76 132.72,111.76 | AC0.A 144.78,197.49 144.78,196.22 AC0.C 144.78,194.94 144.78,193.68 AC0.E 144.78,192.41 144.78,191.13 AC0.H 144.78,189.87 144.78,188.59 AC0.K 144.78,187.32 144.78,186.06 AC0.M 144.78,184.78 144.78,183.51 AC0.P 144.78,182.25 144.78,180.97 AC0.S 144.78,179.71 144.78,178.44 AC0.U 144.78,177.16 144.78,175.9 AC0.W 144.78,174.62 144.78,173.35 AC0.Y 144.78,172.09 144.78,170.81 AC0.AA 144.78,169.54 144.78,168.28 AC0.CC 144.78,167 144.78,165.74 AC0.EE 144.78,164.47 144.78,163.19 AC0.HH 144.78,161.93 144.78,160.66 AC0.KK 144.78,159.38 144.78,158.12 AC0.MM 144.78,156.84 144.78,155.57 AC0.PP 144.78,154.31 144.78,153.03 AC0.SS 144.78,151.76 144.78,150.5 AC0.UU 145.41,149.86 146.69,149.86 AC0.VV 147.32,149.22 147.32,140.34 149.86,137.79 DATA0.A | AC0.B 146.69,198.12 145.41,198.12 AC0.A | BMB1.VV 161.93,149.86 160.66,149.86 BMB1.UU 160.02,150.5 160.02,151.76 BMB1.SS 160.02,153.03 160.02,154.31 BMB1.PP 160.02,155.57 160.02,156.84 BMB1.MM 160.02,158.12 160.02,159.38 BMB1.KK 160.02,160.66 160.02,161.93 BMB1.HH 160.02,163.19 160.02,164.47 BMB1.EE 160.02,165.74 160.02,167 BMB1.CC 160.02,168.28 160.02,169.54 BMB1.AA 160.02,170.81 160.02,172.09 BMB1.Y 160.02,173.35 160.02,174.62 BMB1.W 160.02,175.9 160.02,177.16 BMB1.U 160.02,178.44 160.02,179.71 BMB1.S 160.02,180.97 160.02,182.25 BMB1.P 160.02,183.51 160.02,184.78 BMB1.M 160.02,186.06 160.02,187.32 BMB1.K 160.02,188.59 160.02,189.87 BMB1.H 160.02,191.13 160.02,192.41 BMB1.E 160.02,193.68 160.02,194.94 BMB1.C 160.02,196.22 160.02,197.49 BMB1.A 160.66,198.12 161.93,198.12 BMB1.B 163.19,198.12 174.62,198.12 BMB0.A
  Top 0.635: IC32.8 83.82,194.31 83.82,196.22 89.53,196.22 91.44,194.31 IC32.5 92.08,192.41 93.34,192.41 IC32.4 93.98,191.77 v95.89,189.87 | 73.03,177.16 71.12,177.16 71.12,161.93 C34.2 | 73.03,177.16 78.11,177.16 IC33.10 | 73.03,177.16 73.03,189.23 71.12,191.13 C31.2 | 106.05,163.83 104.14,161.93 C35.2 | 106.05,173.99 106.05,163.83 | 106.05,173.99 104.14,175.9 C33.2 | 106.05,184.78 106.05,173.99 | 106.05,184.78 106.05,189.23 104.14,191.13 C32.2 | 106.05,184.78 114.3,184.78 C99.- 116.84,185.42 128.91,185.42 AC1.M | C25.2 133.35,142.88 132.08,144.15 132.08,149.22 AC1.VV 131.44,149.86 130.18,149.86 AC1.UU 129.54,150.5 129.54,151.76 AC1.SS 129.54,153.03 129.54,154.31 AC1.PP 129.54,155.57 129.54,156.84 AC1.MM 129.54,158.12 129.54,159.38 AC1.KK 129.54,160.66 129.54,161.93 AC1.HH 129.54,163.19 129.54,164.47 AC1.EE 129.54,165.74 129.54,167 AC1.CC 129.54,168.28 129.54,169.54 AC1.AA 129.54,170.81 129.54,172.09 AC1.Y 129.54,173.35 129.54,174.62 AC1.W 129.54,175.9 129.54,177.16 AC1.U 129.54,178.44 129.54,179.71 AC1.S 129.54,180.97 129.54,182.25 AC1.P 129.54,183.51 129.54,184.78 AC1.M | AC1.M 129.54,186.06 129.54,187.32 AC1.K 129.54,188.59 129.54,189.87 AC1.H 129.54,191.13 129.54,192.41 AC1.E 129.54,193.68 129.54,194.94 AC1.C 129.54,196.22 129.54,197.49 AC1.A 130.18,198.12 131.44,198.12 AC1.B 132.72,198.12 144.15,198.12 AC0.A
  Bottom 0.635: IC21.15 69.85,127 78.11,127 DATA2.K | DATA2.E 78.11,132.08 69.85,132.08 IC21.17 67.31,132.08 66.67,132.08 v64.14,134.62 | DATA2.UU 79.38,88.9 80.64,88.9 DATA2.VV | v62.23,111.76 78.11,111.76 DATA2.Y | ADDRESS2.UU 79.38,17.78 80.64,17.78 ADDRESS2.VV | v62.23,40.64 78.11,40.64 ADDRESS2.Y | C5.2 34.92,80.01 34.29,80.01 33.66,80.64 IC5.1 33.02,82.55 26.67,88.9 IC18.8 24.13,88.9 19.05,83.82 13.97,83.82 | 13.97,83.82 9.53,88.27 IC17.7 | 13.97,83.82 15.24,82.55 IC5.8 15.24,80.01 16.51,78.74 19.05,78.74 22.86,74.93 IC5.12 22.86,72.39 19.05,68.58 13.97,68.58 12.7,67.31 IC2.7 | C2.2 31.11,64.77 32.38,66.04 42.55,66.04 ADDRESS3.A 43.81,66.04 45.09,66.04 ADDRESS3.B | IC4.1 31.11,50.16 31.75,50.16 32.38,49.53 C4.2 33.66,49.53 34.92,50.8 42.55,50.8 ADDRESS3.P | 32.38,33.02 31.11,34.29 C1.2 | 32.38,33.02 42.55,33.02 ADDRESS3.EE | IC3.12 20.32,13.97 24.13,17.78 29.21,17.78 30.48,19.05 IC3.1 31.11,19.68 31.75,19.68 32.38,19.05 C3.2 33.66,19.05 34.92,20.32 42.55,20.32 ADDRESS3.SS | IC6.10 59.69,12.7 51.44,12.7 46.35,17.78 ADDRESS3.VV | 32.38,33.02 13.97,33.02 12.7,34.29 IC1.7 | C37.2 38.73,176.53 40.01,175.26 45.09,175.26 SV1.2 | C38.2 38.73,191.77 39.37,192.41 50.16,192.41 IC31.8 50.8,191.77 53.34,189.23 95.25,189.23 v95.89,189.87 96.52,190.5 102.23,190.5 103.5,191.77 C32.2 | C36.2 38.73,161.29 39.37,161.93 52.7,161.93 IC34.7 | IC19.12 34.29,129.54 42.55,129.54 DATA3.H | C19.2 26.04,142.24 16.51,142.24 C97.- | C17.2 12.06,106.68 14.61,109.22 26.04,109.22 C18.2 | IC18.12 34.29,96.52 42.55,96.52 DATA3.MM | DATA3.VV 46.35,88.9 51.44,83.82 59.69,83.82 IC20.10 62.23,83.82 64.14,81.92 69.85,81.92 71.75,83.82 v78.74,83.82 95.25,83.82 IC22.10
  Bottom 0.635: IC19.8 26.67,121.92 29.21,119.38 42.55,119.38 DATA3.S | 184.78,42.55 186.69,40.64 189.23,40.64 190.5,39.37 IC15.12 | 184.78,42.55 182.88,44.45 IC15.8 | 184.78,42.55 v171.45,42.55 | IC15.1 201.29,45.09 201.93,45.09 202.56,44.45 C15.2 203.84,44.45 205.1,45.72 215.26,45.72 ADDRESS.U | IC14.12 190.5,13.97 194.31,17.78 199.39,17.78 200.66,19.05 IC14.1 201.29,19.68 201.93,19.68 202.56,19.05 C14.2 203.84,19.05 205.1,20.32 215.26,20.32 ADDRESS.SS | IC16.1 201.29,70.48 201.93,69.85 202.56,69.85 C16.2 203.84,69.85 207.65,66.04 215.26,66.04 ADDRESS.A | ADDRESS.UU 216.53,17.78 217.81,17.78 ADDRESS.VV | IC28.1 201.29,90.81 201.93,90.81 202.56,90.17 C28.2 203.84,90.17 205.1,91.44 215.26,91.44 DATA.SS | DATA.UU 216.53,88.9 217.81,88.9 DATA.VV | DATA.B 217.81,137.16 216.53,137.16 DATA.A 215.26,137.16 214,138.43 203.84,138.43 C30.2 202.56,138.43 201.93,139.06 201.29,139.06 IC30.1 | C29.2 203.84,114.3 215.26,114.3 DATA.W | IC27.10 168.91,116.84 170.81,114.94 180.97,114.94 182.25,116.2 IC29.8 | v118.75,15.24 122.56,15.24 125.09,12.7 130.81,12.7 IC10.10 | ADDRESS1.UU 114.94,17.78 116.2,17.78 ADDRESS1.VV | ADDRESS1.B 116.2,66.04 114.94,66.04 ADDRESS1.A | v98.42,40.64 113.67,40.64 ADDRESS1.Y | IC23.15 105.41,127 113.67,127 DATA1.K | IC23.17 105.41,132.08 113.67,132.08 DATA1.E | DATA1.B 116.2,137.16 114.94,137.16 DATA1.A | v100.33,111.76 113.67,111.76 DATA1.Y | v121.28,83.82 130.81,83.82 IC24.10 | ADDRESS0.UU 150.5,17.78 151.76,17.78 ADDRESS0.VV | v133.99,40.64 149.22,40.64 ADDRESS0.Y | v152.4,71.12 168.28,71.12 C13.2 | IC25.15 140.97,127 149.22,127 DATA0.K | IC25.17 140.97,132.08 149.22,132.08 DATA0.E
  Bottom 0.635: DATA0.UU 150.5,88.9 151.76,88.9 DATA0.VV | v134.62,111.76 149.22,111.76 DATA0.Y | AC0.B 147.96,198.12 159.38,198.12 BMB1.A | C31.2 71.75,191.77 72.39,192.41 83.19,192.41 IC32.8 | C34.2 71.75,161.29 74.93,161.29 75.56,161.93 78.11,161.93 IC35.10 | SV1.19 69.22,172.72 80.01,172.72 80.64,173.35 80.64,175.26 80.01,175.26 78.74,176.53 IC33.10
IM0\
  Bottom 0.254: AC1.F 132.72,193.04 133.99,191.77 145.41,191.77 146.69,193.04 AC0.F
IM1\
  Bottom 0.254: AC1.L 132.72,187.96 133.99,186.69 145.41,186.69 146.69,187.96 AC0.L
IM2\
  Bottom 0.254: AC1.R 132.72,182.88 133.99,181.61 145.41,181.61 146.69,182.88 AC0.R
IM3\
  Bottom 0.254: AC1.V 132.72,177.8 133.99,176.53 145.41,176.53 146.69,177.8 AC0.V
IM4\
  Bottom 0.254: AC1.Z 132.72,172.72 133.99,171.45 145.41,171.45 146.69,172.72 AC0.Z
IM5\
  Bottom 0.254: AC1.DD 132.72,167.64 133.99,166.37 145.41,166.37 146.69,167.64 AC0.DD
IM6\
  Bottom 0.254: AC1.JJ 132.72,162.56 133.99,161.29 145.41,161.29 146.69,162.56 AC0.JJ
IM7\
  Bottom 0.254: AC1.NN 132.72,157.48 133.99,156.21 145.41,156.21 146.69,157.48 AC0.NN
IM8\
  Bottom 0.254: AC1.TT 132.72,152.4 133.99,151.13 145.41,151.13 146.69,152.4 AC0.TT
IM9\
  Bottom 0.254: AC1.D 132.72,195.58 133.99,194.31 145.41,194.31 146.69,195.58 AC0.D
IM10\
  Bottom 0.254: AC1.J 132.72,190.5 133.99,189.23 145.41,189.23 146.69,190.5 AC0.J
IM11\
  Bottom 0.254: AC1.N 132.72,185.42 133.99,184.15 145.41,184.15 146.69,185.42 AC0.N
INC_MB\
  Bottom 0.254: 79.38,26.67 47.62,26.67 46.35,27.94 ADDRESS3.LL | 79.38,26.67 80.64,27.94 ADDRESS2.LL | 114.94,26.67 116.2,27.94 ADDRESS1.LL | 79.38,26.67 114.94,26.67 | 114.94,26.67 150.5,26.67 151.76,27.94 ADDRESS0.LL 153.03,27.94 154.31,27.94 155.57,26.67 216.53,26.67 217.81,27.94 ADDRESS.LL
INITIALIZE  (via drill 0.61)
  Top 0.254: v64.77,114.3 64.77,119.38 65.41,120.02 65.41,140.97 62.23,144.15 62.23,164.47 60.33,164.47 59.05,163.19 IC34.5 | v50.8,114.3 50.8,102.87 46.99,99.06 46.99,69.22 44.45,66.67 44.45,24.77 45.72,23.5 ADDRESS3.RR
  Bottom 0.254: 114.94,21.59 83.19,21.59 81.92,22.86 ADDRESS2.RR 80.64,22.86 79.38,21.59 48.9,21.59 47.62,22.86 46.35,22.86 ADDRESS3.RR | 114.94,21.59 116.2,22.86 ADDRESS1.RR | 150.5,21.59 151.76,22.86 ADDRESS0.RR | 114.94,21.59 150.5,21.59 | 150.5,21.59 176.53,21.59 179.07,24.13 216.53,24.13 217.81,22.86 ADDRESS.RR | v50.8,114.3 v64.77,114.3
INTERRUPT\
  Bottom 0.254: AC1.X 132.72,175.26 133.99,173.99 145.41,173.99 146.69,175.26 AC0.X
IOP1
  Bottom 0.254: BAC1.T 193.68,180.34 194.94,179.07 206.38,179.07 207.65,180.34 BAC0.T
IOP2
  Bottom 0.254: BAC1.X 193.68,175.26 194.94,173.99 206.38,173.99 207.65,175.26 BAC0.X
IOP4
  Bottom 0.254: BAC1.BB 193.68,170.18 194.94,168.91 206.38,168.91 207.65,170.18 BAC0.BB
N$2
  Bottom 0.254: IC31.6 56.52,192.41 58.42,190.5 93.98,190.5 95.89,192.41 IC32.3
N$3  (via drill 0.61)
  Top 0.254: v75.56,165.1 76.2,164.47 76.2,158.75 78.74,156.21 IC35.11
  Bottom 0.254: v75.56,165.1 58.42,165.1 56.52,163.19 IC34.6
N$4
  Bottom 0.254: IC17.1 11.43,104.14 15.24,100.33 19.05,100.33 19.68,99.69 24.77,99.69 IC18.4
N$6
  Bottom 0.254: IC31.7 53.98,193.68 55.24,194.94 97.16,194.94 98.42,193.68 IC32.2
N$8
  Top 0.254: IC31.9 51.44,186.06 56.52,191.13 64.77,191.13 64.77,194.31 67.94,197.49 101.6,197.49 101.6,194.31 IC32.1
N$10
  Bottom 0.254: IC17.10 19.05,93.98 20.32,95.25 30.48,95.25 31.75,93.98 IC18.11
N$12
  Top 0.254: IC33.3 96.52,179.07 99.06,181.61 99.06,184.15 IC32.15
N$14  (via drill 0.61)
  Top 0.254: v83.82,174.62 83.19,175.26 83.19,175.9 82.55,176.53 82.55,187.32 86.36,191.13 86.36,191.77 IC32.7
  Bottom 0.254: v83.82,174.62 82.55,174.62 82.55,168.91 83.19,168.28 94.61,168.28 95.89,169.54 IC33.18
N$16  (via drill 0.61)
  Top 0.254: v92.71,182.88 92.71,176.53 93.34,175.9 93.34,172.09 93.98,171.45 IC33.17
  Bottom 0.254: v92.71,182.88 92.08,183.51 85.72,183.51 84.45,184.78 IC32.9
N$18
  Top 0.254: IC33.14 86.36,171.45 85.09,172.72 85.09,182.88 86.36,184.15 IC32.10
N$19
  Bottom 0.254: IC17.4 11.43,96.52 12.7,97.79 21.59,97.79 22.86,96.52 24.13,96.52 IC18.5
N$20  (via drill 0.61)
  Top 0.254: v87,174.62 87.63,175.26 87.63,180.97 88.9,182.25 88.9,184.15 IC32.11
  Bottom 0.254: v87,174.62 83.82,171.45 IC33.13
N$21
  Bottom 0.254: IC17.13 19.05,101.6 20.32,100.33 30.48,100.33 31.75,99.06 IC18.13
N$22
  Bottom 0.254: IC33.8 84.45,178.44 86.36,180.34 92.71,180.34 95.25,182.88 95.25,187.32 93.34,187.32 92.08,186.06 IC32.12
N$24  (via drill 0.61)
  Top 0.254: v87,181.61 87,179.71 86.36,179.07 IC33.7
  Bottom 0.254: v87,181.61 92.71,181.61 93.98,182.88 93.98,184.15 IC32.13
N$26
  Top 0.254: IC33.4 93.98,179.07 96.52,181.61 96.52,184.15 IC32.14
N$27  (via drill 0.61)
  Top 0.254: v68.58,168.91 68.58,167.64 64.14,163.19 IC34.3
  Bottom 0.254: v68.58,168.91 69.22,169.54 78.11,169.54 IC33.11
N$31
  Bottom 0.254: IC4.4 22.86,52.07 22.86,56.52 26.04,56.52 26.67,57.15 26.67,65.41 27.3,65.41 IC2.1
N$33
  Top 0.254: IC4.11 17.78,44.45 16.51,45.72 16.51,55.88 17.78,57.15 IC2.10
N$34
  Top 0.254: IC4.5 20.32,52.07 19.05,53.34 19.05,62.23 20.32,63.5 20.32,64.77 IC2.4
N$36
  Top 0.254: IC4.13 22.86,44.45 24.13,45.72 24.13,55.88 25.4,57.15 IC2.13
N$37
  Top 0.254: IC3.4 22.86,21.59 23.5,22.23 23.5,26.04 24.13,26.67 24.13,30.48 27.94,34.29 IC1.1
N$38
  Top 0.254: IC3.11 17.78,13.97 16.51,15.24 16.51,25.4 17.78,26.67 IC1.10
N$39
  Top 0.254: IC3.5 20.32,21.59 19.05,22.86 19.05,33.02 20.32,34.29 IC1.4
N$41
  Top 0.254: IC3.13 22.86,13.97 24.13,15.24 24.13,25.4 25.4,26.67 IC1.13
POWER_CLEAR
  Bottom 0.254: BAC1.RR 193.68,154.94 194.94,153.67 206.38,153.67 207.65,154.94 BAC0.RR
RUN
  Bottom 0.254: AC1.FF 132.72,165.1 133.99,163.83 145.41,163.83 146.69,165.1 AC0.FF
SKIP\
  Bottom 0.254: AC1.T 132.72,180.34 133.99,179.07 145.41,179.07 146.69,180.34 AC0.T
UNUSED1
  Bottom 0.254: AC1.RR 132.72,154.94 133.99,153.67 145.41,153.67 146.69,154.94 AC0.RR
VCC  (via drill 0.61)
  Top 0.635: v94.61,40.64 94.61,40.01 92.71,38.1 RN18.1 | v99.69,41.91 102.87,38.73 C8.1 102.87,37.47 102.87,36.83 103.5,36.2 IC8.20 | C9.1 103.5,71.12 103.5,69.22 IC9.20 105.41,68.58 107.31,66.67 v107.31,43.18 | IC26.20 174.62,107.31 173.99,107.95 173.99,108.58 C26.1 | IC29.16 201.29,109.22 202.56,109.22 C29.1 | C29.1 203.2,109.86 205.1,111.76 205.1,126.36 200.66,130.81 IC30.16 | C13.1 173.99,70.48 174.62,69.85 174.62,69.22 IC13.20 | IC11.20 139.06,69.22 139.06,69.85 138.43,70.48 C11.1 138.43,71.75 138.43,73.03 139.06,73.66 142.88,73.66 v142.88,35.56 142.88,8.89 141.6,7.62 C98.+ | C16.1 203.2,65.41 205.1,67.31 205.1,78.11 200.66,82.55 IC28.16 | v129.54,40.01 129.54,39.37 128.27,38.1 RN16.1 | v136.53,41.91 138.43,40.01 138.43,38.73 C10.1 138.43,37.47 138.43,36.83 139.06,36.2 IC10.20 | IC12.20 174.62,36.2 173.99,36.83 173.99,37.47 C12.1 | 205.1,32.38 205.1,16.51 203.2,14.61 C14.1 | 205.1,32.38 200.66,36.83 IC15.16 | 205.1,32.38 205.1,57.78 200.66,62.23 IC16.16 | C29.1 203.2,108.58 205.74,106.05 205.74,88.27 203.2,85.72 C28.1 | v127.64,73.66 127.64,69.22 RN15.1 | IC24.20 139.06,107.31 138.43,107.95 138.43,108.58 C24.1 138.43,109.86 138.43,111.76 v137.16,113.03 137.16,119.38 136.53,120.02 136.53,138.43 139.06,140.97 | IC27.20 174.62,140.34 174.62,140.97 173.99,141.6 C27.1 173.35,142.24 170.81,144.78 165.1,144.78 165.1,142.24 163.19,140.34 RN1.1 | 139.06,140.97 138.43,141.6 C25.1 | 139.06,140.97 139.06,140.34 IC25.20 | IC32.6 88.9,191.77 92.71,187.96 101.6,187.96 101.6,186.69 IC32.16 101.6,184.15 101.6,179.07 IC33.1 101.6,176.53 101.6,171.45 IC33.20 101.6,168.91 101.6,163.83 IC35.1 101.6,161.29 101.6,156.21 IC35.20 101.6,153.67 102.87,152.4 102.87,142.88 C23.1 102.87,141.6 102.87,140.97 103.5,140.34 IC23.20 105.41,139.7 107.31,137.79 v107.31,110.49
  Top 0.635: v92.71,113.03 92.71,110.49 92.08,109.86 RN8.1 | IC22.20 103.5,107.31 102.87,107.95 102.87,108.58 C22.1 | C6.1 67.31,37.47 67.94,36.83 67.94,36.2 IC6.20 | C96.+ 71.12,7.62 71.12,26.04 71.75,26.67 v71.75,35.56 v71.75,68.58 | C7.1 67.31,70.48 67.94,69.85 67.94,69.22 IC7.20 | v50.8,68.58 50.8,49.53 52.7,47.62 52.7,41.27 55.24,38.73 RN20.1 | v56.52,111.76 56.52,109.86 RN10.1 | v66.67,113.03 67.31,112.39 67.31,109.86 C20.1 67.31,108.58 67.31,107.95 67.94,107.31 IC20.20 | IC34.1 68.58,161.29 68.58,156.21 IC34.14 68.58,153.67 68.58,140.34 IC21.20 | C21.1 67.31,141.6 67.94,140.97 67.94,140.34 IC21.20 | v71.75,114.94 71.75,137.79 69.85,139.7 IC21.20 | C2.1 30.48,60.33 33.02,62.87 v33.02,68.58 33.02,72.39 IC5.16 | C3.1 33.02,14.61 34.92,16.51 34.92,24.13 30.48,28.57 C1.1 30.48,29.84 33.02,32.38 33.02,43.81 C4.1 33.02,45.09 34.92,46.99 34.92,50.16 27.94,57.15 IC2.14 | SV1.20 68.58,175.9 68.58,184.15 IC31.16 | 40.01,168.91 40.01,158.75 38.1,156.84 C36.1 38.1,155.57 38.1,123.83 30.48,116.2 | 40.01,168.91 38.1,170.81 C37.1 | 40.01,168.91 40.01,184.15 38.1,186.06 C38.1 | C19.1 31.75,141.6 32.38,140.97 32.38,140.34 IC19.16 31.75,139.7 30.48,138.43 30.48,116.2 | IC18.16 32.38,107.31 32.38,107.95 31.75,108.58 C18.1 31.75,109.86 30.48,111.12 30.48,116.2 | IC17.14 17.14,104.78 17.14,105.41 16.51,106.05 C17.1 16.51,107.31 15.88,107.95 15.88,118.11 C97.+ | 30.48,116.2 39.37,107.31 39.37,79.38 35.56,75.56 C5.1 | v88.9,144.15 88.9,142.24 90.81,140.34 RN7.1 | v156.21,139.7 156.21,115.57 161.93,109.86 RN2.1
  Bottom 0.635: v94.61,40.64 95.89,41.91 v99.69,41.91 100.97,43.18 v107.31,43.18 | RN15.1 125.73,68.58 105.41,68.58 IC9.20 | RN2.1 163.83,109.22 165.74,111.12 171.45,111.12 173.35,109.22 C26.1 | IC30.16 201.29,132.72 201.93,133.35 202.56,133.35 C30.1 | IC26.20 176.53,106.68 181.61,111.76 199.39,111.76 200.66,110.49 IC29.16 | RN13.1 161.29,68.58 140.97,68.58 IC11.20 | 141.6,72.39 140.34,71.12 139.06,71.12 C11.1 | 141.6,72.39 142.24,73.03 171.45,73.03 173.35,71.12 C13.1 | IC16.16 201.29,64.14 201.93,64.77 202.56,64.77 C16.1 | IC28.16 201.29,84.45 201.93,85.09 202.56,85.09 C28.1 | v129.54,40.01 131.44,41.91 v136.53,41.91 | RN14.1 163.83,38.1 165.74,40.01 171.45,40.01 173.35,38.1 C12.1 | C14.1 202.56,13.97 201.93,13.97 201.29,13.34 IC14.16 200.66,11.43 198.12,8.89 144.15,8.89 142.24,6.99 C98.+ | C15.1 202.56,39.37 201.93,39.37 201.29,38.73 IC15.16 200.66,36.83 198.75,34.92 177.16,34.92 176.53,35.56 IC12.20 | v142.88,35.56 140.97,35.56 IC10.20 | v127.64,73.66 140.34,73.66 141.6,72.39 | v137.16,113.03 127,113.03 127,109.86 RN6.1 | RN1.1 161.29,139.7 v156.21,139.7 140.97,139.7 IC25.20 | IC32.16 102.23,186.06 102.87,186.69 103.5,186.69 C32.1 | IC35.20 102.23,155.57 102.87,156.21 103.5,156.21 C35.1 | IC33.20 102.23,170.81 102.87,171.45 103.5,171.45 C33.1 | C99.+ 114.3,163.19 102.23,163.19 IC35.1 | v92.71,113.03 97.16,113.03 100.33,109.86 102.87,109.86 C22.1 103.5,109.22 104.78,110.49 v107.31,110.49 | RN5.1 125.73,139.7 105.41,139.7 IC23.20 | C25.1 137.79,142.24 135.25,144.78 118.75,144.78 116.2,142.24 103.5,142.24 C23.1 102.23,142.24 100.33,144.15 v88.9,144.15 | v71.75,35.56 69.85,35.56 IC6.20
